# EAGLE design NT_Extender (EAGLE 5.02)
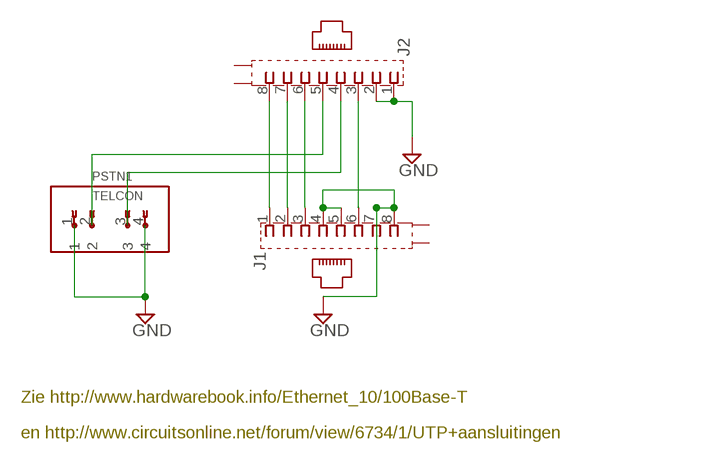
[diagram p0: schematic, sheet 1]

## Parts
J1  555141-1  [555153-1]
J2  555141-1  [555153-1]
PSTN1  TELCON  [CON_T]

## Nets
GND: J1.4 J1.5 J1.7 J1.8 J2.1 J2.2 PSTN1.1 PSTN1.4
N$1: J1.1 J2.8
N$2: J1.2 J2.7
N$3: J1.3 J2.6
N$4: J1.6 J2.3
N$5: J2.5 PSTN1.2
N$6: J2.4 PSTN1.3
Unconnected: J1.G1(S1) J1.G2(S2) J2.G1(S1) J2.G2(S2)

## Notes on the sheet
- Zie http://www.hardwarebook.info/Ethernet_10/100Base-T
- en http://www.circuitsonline.net/forum/view/6734/1/UTP+aansluitingen

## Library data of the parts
J1 J2 = con-amp:555141-1: AMP connector
PSTN1 = bernard:TELCON

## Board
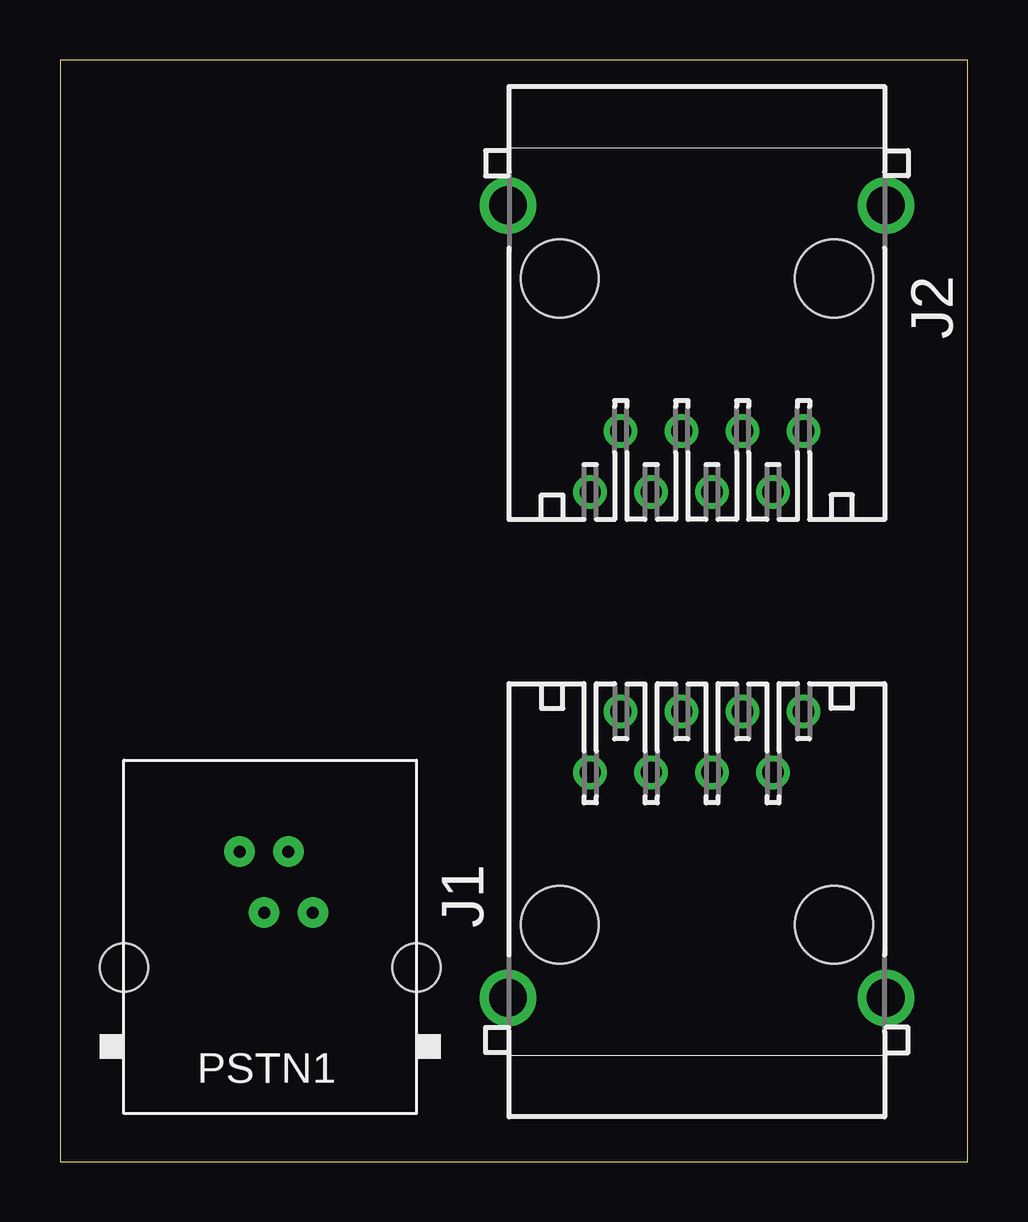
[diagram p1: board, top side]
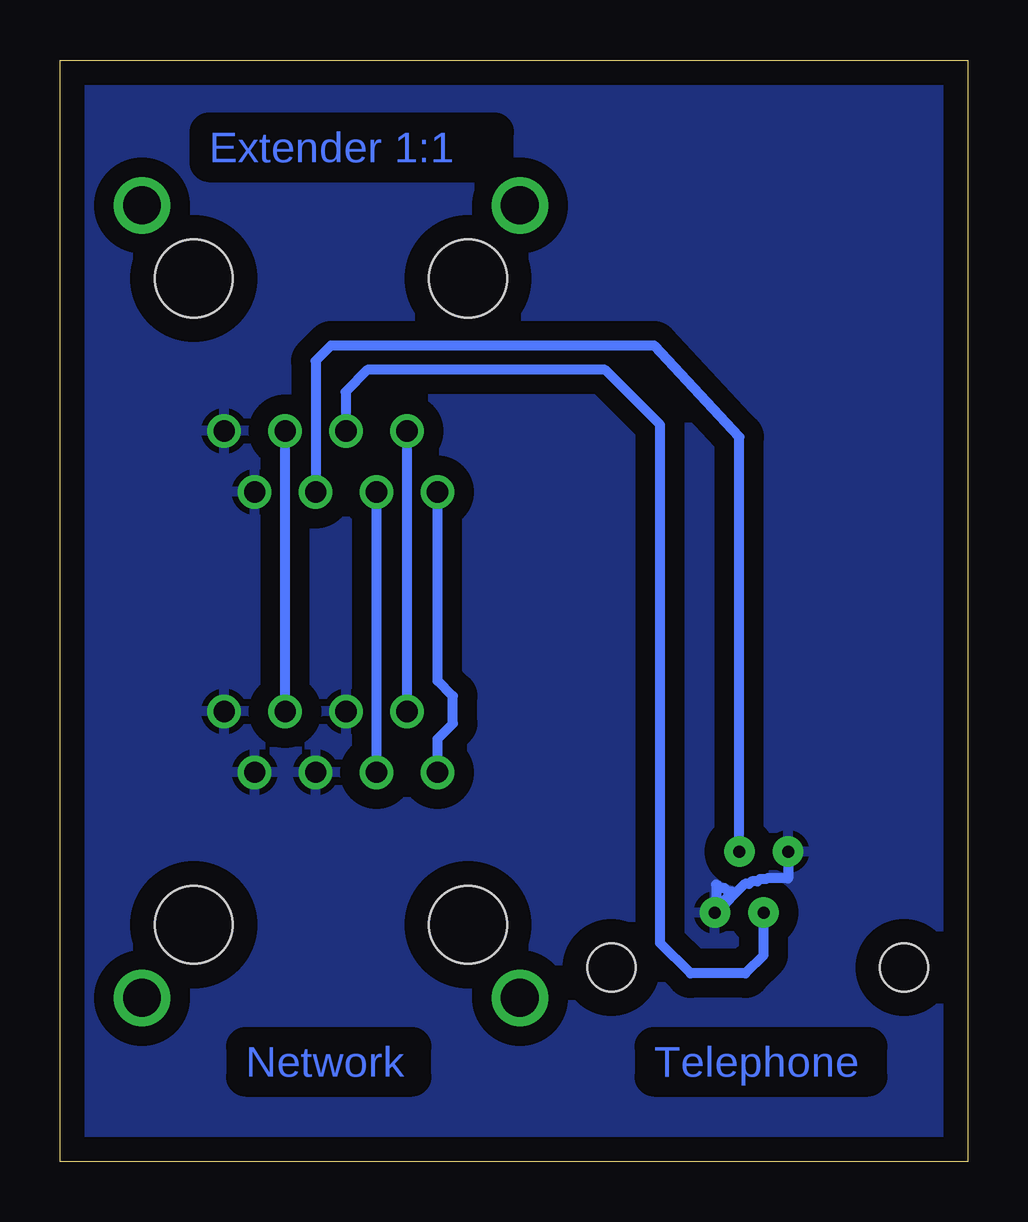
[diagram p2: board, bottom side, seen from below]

Size 37.83 x 45.9 mm. Coordinates in mm from the lower left corner, seen from the top.
Outline: 0,0 37.83,0 37.83,45.9 0,45.9 0,0
Copper layers (1*16): Top 0.035mm / dielectric 1.5mm / Bottom 0.035mm
Design rules "default": minimum track width 10mil, minimum drill 24mil, track to track 8mil, track to pad 8mil, pad to pad 8mil, via to via 8mil, smd to smd 8mil, copper to edge 40mil, drill to drill 8mil, minimum pad ring 10mil, minimum via ring 8mil, stop-mask expansion 4mil, vias tented up to drill 0mil, thermal gap 10mil

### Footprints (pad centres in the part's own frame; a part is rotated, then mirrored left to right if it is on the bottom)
555153-1 = drill 0.889 round: 1 -4.445,6.35; 2 -3.175,8.89; 3 -1.905,6.35; 4 -0.635,8.89; 5 0.635,6.35; 6 1.905,8.89; 7 3.175,6.35; 8 4.445,8.89 | drill 1.575 pad 2.184 round: G1 -7.874,-3.048; G2 7.874,-3.048 | hole 3.251: -5.715,0; 5.715,0
CON_T = drill 0.5 pad 1.27 round: 1 -1.27,3.556; 2 -0.254,1.016; 3 0.762,3.556; 4 1.778,1.016 | hole 2: 6.096,-1.27; -6.096,-1.27

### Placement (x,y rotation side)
J1  26.54,9.87 0 top
J2  26.54,36.79 180 top
PSTN1  8.76,9.36 0 top

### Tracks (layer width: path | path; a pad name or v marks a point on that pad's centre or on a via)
GND
  Bottom 0.406: 7.56,12.94 7.51,12.94 PSTN1.1 7.49,11.8 8.38,11.8 8.4,11.77 8.66,11.77 8.76,11.67 9.01,11.67 9.11,11.57 9.29,11.57 10.51,10.35 10.51,10.53 9.8,11.24 9.98,11.24 10.13,11.39 10.33,11.39 10.48,11.54 10.48,10.43 PSTN1.4
  pour Bottom (isolate 0.813): 0.63,46.19 37.97,46.19 38.35,-1.51 1.01,-1.51
N$1
  Bottom 0.406: J1.1 22.09,17.61 21.46,18.25 21.46,19.39 22.09,20.03 J2.8
N$2
  Bottom 0.406: 23.36,30.57 J2.7 J1.2
N$3
  Bottom 0.406: J2.6 24.63,27.77 24.76,27.65 24.63,27.52 J1.3
N$4
  Bottom 0.406: J1.6 J2.3
N$5
  Bottom 0.406: PSTN1.2 8.5,8.6 9.27,7.84 11.55,7.84 12.82,9.11 12.82,30.7 15.11,32.98 25.01,32.98 25.93,32.07 25.93,30.44 J2.5
N$6
  Bottom 0.406: PSTN1.3 9.52,30.19 13.08,34 26.54,34 27.17,33.36 J2.4 27.17,27.88

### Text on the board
Bottom: Extender 1:1 | Telephone | Network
